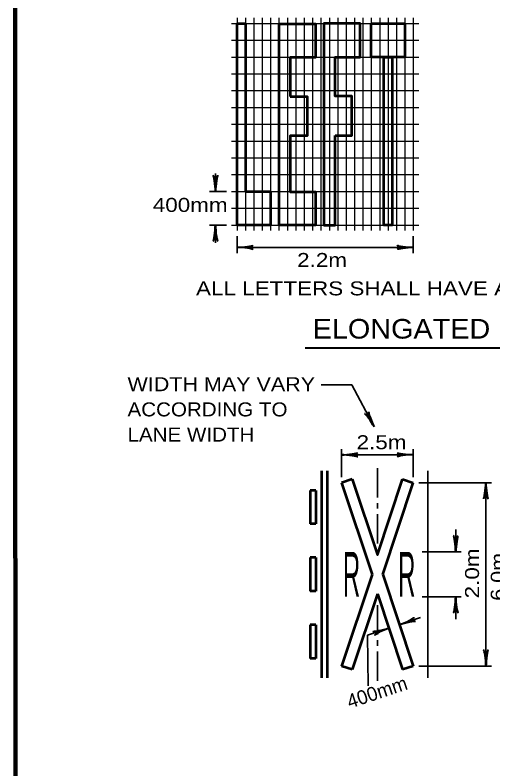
# Model space of a CAD drawing. Extents: x -96 to 617, y -65 to 388.
# Drawn here: x -47.9 to 37.5, y 126.1 to 260.8 of the extents above; entities that cross this region are included whole.
import ezdxf

# ---------------------------------------------------------------- set-up
doc = ezdxf.new("R2010")
doc.units = 0
doc.layers.add('1', color=7, linetype='Continuous', lineweight=53)

msp = doc.modelspace()

# ---------------------------------------------------------------- linework, layer by layer
at = {"layer": '1', "lineweight": 25}
for p, q in [((-8.21, 260.267), (-8.21, 222.267)), ((-6.71, 260.267), (-6.71, 222.267)), ((-5.21, 260.267), (-5.21, 222.267)), ((-3.71, 260.267), (-3.71, 222.267)), ((-2.21, 260.267), (-2.21, 222.267)), ((-0.71, 222.267), (-0.71, 260.267)), ((0.79, 260.267), (0.79, 222.267)), ((2.29, 260.267), (2.29, 222.267)), ((3.79, 260.267), (3.79, 222.267)), ((5.29, 260.267), (5.29, 222.267)), ((6.79, 260.267), (6.79, 222.267)), ((8.29, 260.267), (8.29, 222.267)), ((9.79, 260.267), (9.79, 222.267)), ((11.29, 260.267), (11.29, 222.267)), ((12.79, 260.267), (12.79, 222.267)), ((14.29, 260.267), (14.29, 222.267)), ((15.79, 260.267), (15.79, 222.267)), ((17.29, 260.267), (17.29, 222.267)), ((18.79, 260.267), (18.79, 222.267)), ((20.29, 260.267), (20.29, 222.267)), ((21.79, 260.267), (21.79, 222.267)), ((23.29, 260.267), (23.29, 222.267)), ((-9.21, 259.267), (24.29, 259.267)), ((-9.21, 256.267), (24.29, 256.267)), ((-9.21, 253.267), (24.29, 253.267)), ((-9.21, 250.267), (24.29, 250.267)), ((-9.21, 247.267), (24.29, 247.267)), ((-9.21, 244.267), (24.29, 244.267)), ((-9.21, 241.267), (24.29, 241.267)), ((-9.21, 238.267), (24.29, 238.267)), ((-9.21, 235.267), (24.29, 235.267)), ((-9.21, 232.267), (24.29, 232.267)), ((-9.21, 229.267), (24.29, 229.267)), ((-9.21, 226.267), (24.29, 226.267)), ((-9.21, 223.267), (24.29, 223.267))]:
    msp.add_line(p, q, dxfattribs=at)
at = {"layer": '1', "lineweight": 35}
for p, q in [((-12.07, 232.492), (-12.07, 229.267)), ((-10.11, 229.267), (-13.11, 229.267)), ((-10.11, 223.267), (-13.11, 223.267)), ((-12.07, 223.267), (-12.07, 220.094)), ((-8.21, 218.267), (-8.21, 221.267)), ((23.29, 218.267), (23.29, 221.267)), ((-8.21, 219.267), (23.29, 219.267)), ((10.484, 178.227), (10.484, 183.227)), ((23.279, 178.227), (23.279, 183.227)), ((10.484, 182.227), (23.279, 182.227)), ((16.881, 179.859), (16.881, 174.609)), ((24.279, 177.227), (37.279, 177.227)), ((36.279, 177.227), (36.279, 144.492)), ((16.881, 173.609), (16.881, 172.609)), ((16.881, 171.609), (16.881, 166.359)), ((30.881, 164.859), (30.881, 168.859)), ((24.881, 164.859), (31.881, 164.859)), ((24.881, 156.859), (31.881, 156.859)), ((30.881, 156.859), (30.881, 152.859)), ((16.881, 155.359), (16.881, 150.109)), ((24.612, 153.142), (20.817, 151.877)), ((18.919, 151.244), (15.125, 149.98)), ((15.125, 149.98), (15.219, 140.931)), ((16.881, 149.109), (16.881, 148.109)), ((16.881, 147.109), (16.881, 141.859)), ((24.279, 144.492), (37.279, 144.492))]:
    msp.add_line(p, q, dxfattribs=at)
at = {"layer": '1', "lineweight": 40}
msp.add_line((3.989, 201.338), (63.905, 201.338), dxfattribs=at)
at = {"layer": '1'}
for p, q in [((6.881, 179.359), (6.881, 142.359)), ((7.881, 179.359), (7.881, 142.359)), ((12.381, 177.859), (10.484, 177.227)), ((21.381, 177.859), (23.279, 177.227)), ((10.484, 177.227), (15.94, 160.859)), ((17.823, 160.859), (23.279, 177.227)), ((5.881, 175.859), (4.881, 175.859)), ((4.881, 175.859), (4.881, 169.859)), ((5.881, 175.859), (5.881, 169.859)), ((5.881, 169.859), (4.881, 169.859)), ((5.881, 163.859), (4.881, 163.859)), ((4.881, 163.859), (4.881, 157.859)), ((5.881, 163.859), (5.881, 157.859)), ((15.94, 160.859), (10.484, 144.492)), ((17.823, 160.859), (23.279, 144.492)), ((5.881, 157.859), (4.881, 157.859)), ((16.881, 157.359), (12.381, 143.859)), ((16.881, 157.359), (21.381, 143.859)), ((5.881, 151.859), (4.881, 151.859)), ((4.881, 151.859), (4.881, 145.859)), ((5.881, 151.859), (5.881, 145.859)), ((5.881, 145.859), (4.881, 145.859)), ((12.381, 143.859), (10.484, 144.492)), ((23.279, 144.492), (21.381, 143.859))]:
    msp.add_line(p, q, dxfattribs=at)
at = {"layer": '1', "lineweight": 158}
msp.add_lwpolyline([(611.853, 383.009), (-47.897, 382.926), (-47.814, -55.407)], dxfattribs=at)
at = {"layer": '1'}
for points in [[(-6.71, 259.267), (-6.71, 229.267), (-2.21, 229.267), (-2.21, 223.267), (-8.21, 223.267), (-8.21, 259.267)], [(1.312, 246.214), (4.312, 246.214), (4.312, 239.214), (1.312, 239.214), (1.312, 229.214), (5.812, 229.214), (5.812, 223.214), (-0.688, 223.214), (-0.688, 259.214), (5.812, 259.214), (5.812, 253.214), (1.312, 253.214)], [(9.313, 239.259), (12.313, 239.259), (12.313, 246.259), (9.313, 246.259), (9.313, 253.259), (13.813, 253.259), (13.813, 259.259), (7.313, 259.259), (7.313, 223.259), (9.313, 223.26), (9.313, 239.079)], [(15.79, 259.267), (21.79, 259.267), (21.79, 253.267), (15.79, 253.267)], [(18.04, 223.267), (18.04, 253.267), (19.54, 253.267), (19.54, 223.267)], [(19.54, 253.267), (19.54, 223.267), (18.04, 223.267), (18.04, 253.267)]]:
    msp.add_lwpolyline(points, close=True, dxfattribs=at)
at = {"layer": '1', "lineweight": 35}
for points in [[(6.804, 194.702), (12.3, 194.702), (16.296, 187.198)], [(25.881, 179.359), (25.881, 148.762), (25.881, 142.359)]]:
    msp.add_lwpolyline(points, dxfattribs=at)
at = {"layer": '1'}
msp.add_lwpolyline([(12.381, 177.859), (16.881, 164.359), (21.381, 177.859)], dxfattribs=at)
at = {"layer": '1', "lineweight": 40}
for centre, major_axis, ratio, start_param, end_param in [((-12.346, 230.358), (0.156, -1.786), 0.122415, 0.8963533, 3.1415927), ((-11.858, 230.388), (-0.176, -1.756), 0.07063, 3.1407148, 5.41811), ((-12.282, 222.147), (0.176, 1.756), 0.07063, 3.1407148, 5.41811), ((-11.794, 222.176), (-0.156, 1.786), 0.122415, 0.8963533, 3.1415927), ((-7.089, 219.479), (-1.756, -0.176), 0.07063, 0.8650754, 3.1424706), ((-7.089, 219.479), (-1.756, -0.176), 0.07063, 0.8650754, 3.1424706), ((22.199, 219.543), (1.786, -0.156), 0.122415, 3.1415927, 5.386832), ((-7.118, 218.991), (-1.786, 0.156), 0.122415, 3.1415927, 5.386832), ((-7.118, 218.991), (-1.786, 0.156), 0.122415, 3.1415927, 5.386832), ((22.17, 219.056), (1.756, 0.176), 0.07063, 0.8650754, 3.1424706), ((15.956, 188.287), (-0.67, 1.633), 0.07063, 6.2823074, 8.5597026), ((15.539, 188.032), (0.977, -1.503), 0.122415, 0.8963533, 3.1415927), ((11.575, 182.503), (-1.786, -0.156), 0.122415, 0.8963533, 3.1415927), ((11.575, 182.503), (-1.786, -0.156), 0.122415, 0.8963533, 3.1415927), ((11.605, 182.015), (-1.756, 0.176), 0.07063, 3.1407148, 5.41811), ((11.605, 182.015), (-1.756, 0.176), 0.07063, 3.1407148, 5.41811), ((22.188, 181.95), (1.786, 0.156), 0.122415, 0.8963533, 3.1415927), ((22.188, 181.95), (1.786, 0.156), 0.122415, 0.8963533, 3.1415927), ((22.158, 182.438), (1.756, -0.176), 0.07063, 3.1407148, 5.41811), ((22.158, 182.438), (1.756, -0.176), 0.07063, 3.1407148, 5.41811), ((36.067, 176.106), (0.176, 1.756), 0.07063, 3.1407148, 5.41811), ((36.067, 176.106), (0.176, 1.756), 0.07063, 3.1407148, 5.41811), ((36.555, 176.135), (-0.156, 1.786), 0.122415, 0.8963533, 3.1415927), ((36.555, 176.135), (-0.156, 1.786), 0.122415, 0.8963533, 3.1415927), ((30.605, 165.95), (0.156, -1.786), 0.122415, 0.8963533, 3.1415927), ((30.605, 165.95), (0.156, -1.786), 0.122415, 0.8963533, 3.1415927), ((31.093, 165.98), (-0.176, -1.756), 0.07063, 3.1407148, 5.41811), ((31.093, 165.98), (-0.176, -1.756), 0.07063, 3.1407148, 5.41811), ((30.67, 155.738), (0.176, 1.756), 0.07063, 3.1407148, 5.41811), ((30.67, 155.738), (0.176, 1.756), 0.07063, 3.1407148, 5.41811), ((31.158, 155.768), (-0.156, 1.786), 0.122415, 0.8963533, 3.1415927), ((31.158, 155.768), (-0.156, 1.786), 0.122415, 0.8963533, 3.1415927), ((21.765, 152.484), (-1.645, -0.713), 0.122415, 0.8963533, 3.1415927), ((21.765, 152.484), (-1.645, -0.713), 0.122415, 0.8963533, 3.1415927), ((21.947, 152.03), (-1.722, -0.389), 0.07063, 3.1407148, 5.41811), ((21.947, 152.03), (-1.722, -0.389), 0.07063, 3.1407148, 5.41811), ((17.79, 151.091), (-1.722, -0.389), 0.07063, 6.2823074, 8.5597026), ((17.972, 150.637), (1.645, 0.713), 0.122415, 0.8963533, 3.1415927), ((36.002, 145.583), (0.156, -1.786), 0.122415, 0.8963533, 3.1415927), ((36.002, 145.583), (0.156, -1.786), 0.122415, 0.8963533, 3.1415927), ((36.49, 145.612), (-0.176, -1.756), 0.07063, 3.1407148, 5.41811), ((36.49, 145.612), (-0.176, -1.756), 0.07063, 3.1407148, 5.41811)]:
    msp.add_ellipse(centre, major_axis=major_axis, ratio=ratio, start_param=start_param, end_param=end_param, dxfattribs=at)

# ---------------------------------------------------------------- texts
at = {"layer": '1'}
for s, height, width, p in [('400mm', 2.5, 1.2, (-23.278, 225.607)), ('2.2m', 2.5, 1.2, (2.525, 215.769)), ('ALL LETTERS SHALL HAVE A MIN. HEIGHT OF 2.5m', 2.5, 1.2, (-15.545, 210.698)), ('ELONGATED LETTERS', 3.5, 1.1, (5.302, 202.981)), ('WIDTH MAY VARY', 2.5, 1.15, (-27.793, 193.58)), ('ACCORDING TO', 2.5, 1.1, (-27.793, 189.08)), ('LANE WIDTH', 2.5, 1.1, (-27.793, 184.58)), ('2.5m', 2.5, 1.2, (13.157, 183.217)), ('R', 8, 0.4, (10.708, 156.878)), ('R', 8, 0.4, (20.582, 156.878))]:
    msp.add_text(s, height=height, dxfattribs=dict(at, width=width)).set_placement(p)
for s, width, p in [('2.0m', 1.2, (35.048, 156.572)), ('6.0m', 1.15, (39.636, 156.148))]:
    msp.add_text(s, height=2.5, rotation=90, dxfattribs=dict(at, width=width)).set_placement(p)
msp.add_text('400mm', height=2.5, rotation=18.434, dxfattribs=at).set_placement((11.928, 136.857))

doc.saveas('drawing.dxf')
